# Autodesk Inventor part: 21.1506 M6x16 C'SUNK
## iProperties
Created: 2006-12
Part Number: 21.1506 M6x16 C'SUNK
Material: Steel, Mild
Description: Hexagon socket countersunk head cap screws
Document SubType Name: Modeling
Standard: DIN 7991
Designer: Andy Moles
Standards Organization: DIN
Language: en-US
Size Designation: M6x16
Categories: <MemberInstance Version="R10.0.0"><Categories><Category DisplayName="Fasteners" InternalName="e4da775c-781d-43d5-af7c-5136215cf5a6" Mnemonic="FSTN"><Category Di
Density: 7.86 g/cm^3
Mass: 4.35526 g
Surface Area: 5.4059 cm^2
Volume: 0.554104 cm^3
Author: Andy Moles
Revision Number: 1
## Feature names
1. Revolution1
2. Extrusion1
3. Fillet1
4. Chamfer1
